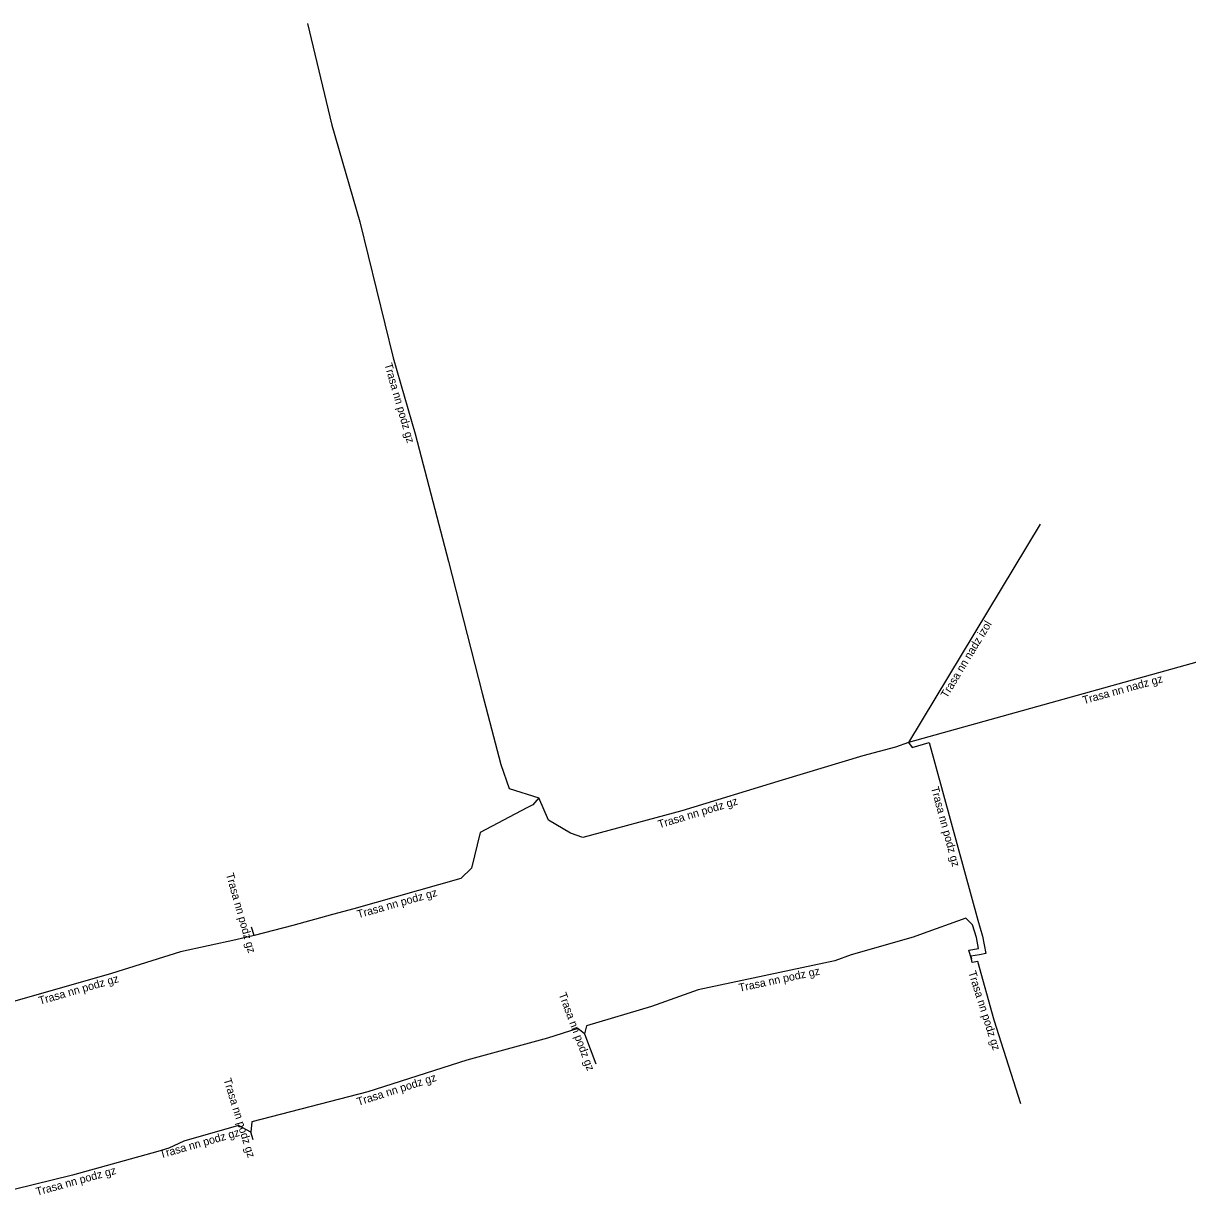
# Model space of a CAD drawing. Extents: x -690200 to -689130, y -975255 to -974631.
# Drawn here: x -689979.9 to -689907.2, y -975138.2 to -975064.6 of the extents above; entities that cross this region are included whole.
import ezdxf

# ---------------------------------------------------------------- set-up
doc = ezdxf.new("R2010")
doc.units = 0
doc.layers.add('Popiskový text - Ostatní atributy Trasy', color=7, linetype='Continuous')
doc.layers.add('Spojnice NN', color=7, linetype='Continuous')

msp = doc.modelspace()

# ---------------------------------------------------------------- linework, layer by layer
at = {"layer": 'Spojnice NN'}
for points in [[(-689962.19, -975064.64), (-689960.67, -975070.98), (-689958.92, -975077.03), (-689956.83, -975085.53), (-689955.46, -975090.27), (-689953.38, -975098.24), (-689951.28, -975106.48), (-689950.11, -975110.93), (-689949.59, -975112.43), (-689947.73, -975113.02)], [(-689916.41, -975095.912), (-689924.64, -975109.55)], [(-689895.57, -975101.45), (-689924.64, -975109.55)], [(-689924.64, -975109.55), (-689925.44, -975109.86), (-689927.49, -975110.39), (-689932.53, -975111.91), (-689938.8, -975113.82), (-689944.98, -975115.5), (-689945.76, -975115.23), (-689947.13, -975114.41), (-689947.73, -975113.02)], [(-689924.64, -975109.55), (-689924.4, -975109.87), (-689923.34, -975109.56), (-689920.305, -975120.666), (-689920.005, -975121.653), (-689919.808, -975122.74), (-689920.201, -975122.816), (-689920.733, -975122.902), (-689920.707, -975123.1)], [(-689947.73, -975113.02), (-689948.11, -975113.45), (-689948.49, -975113.64), (-689951.41, -975115.19), (-689951.94, -975117.4), (-689952.61, -975118.05), (-689959.29, -975119.95), (-689960.62, -975120.3), (-689963.11, -975121), (-689965.53, -975121.62)], [(-689920.707, -975123.1), (-689920.876, -975122.524), (-689920.273, -975122.433), (-689920.395, -975121.747), (-689920.635, -975120.954), (-689921.05, -975120.54), (-689923.94, -975121.58), (-689924.35, -975121.73), (-689928.21, -975122.82), (-689929.24, -975123.2), (-689937.78, -975125.02), (-689940.69, -975126.06), (-689944.76, -975127.25), (-689944.88, -975127.77)], [(-689965.53, -975121.62), (-689966.66, -975121.88), (-689970.12, -975122.63), (-689974.43, -975123.98), (-689981.07, -975125.89), (-689984.56, -975126.73), (-689985.1, -975126.41)], [(-689965.53, -975121.62), (-689965.68, -975121.09)], [(-689917.62, -975132.13), (-689919.28, -975126.9), (-689920.295, -975123.247), (-689920.648, -975123.311), (-689920.707, -975123.1)], [(-689944.88, -975127.77), (-689945.29, -975127.42), (-689947.19, -975128.04), (-689952.23, -975129.41), (-689958.43, -975131.39), (-689965.67, -975133.26), (-689965.74, -975133.9)], [(-689944.88, -975127.77), (-689944.18, -975129.64)], [(-689965.74, -975133.9), (-689966.5, -975133.48), (-689969.92, -975134.46)], [(-689965.59, -975134.38), (-689965.74, -975133.9)], [(-689969.92, -975134.46), (-689970.85, -975134.91), (-689971.54, -975135.12), (-689976.87, -975136.59), (-689980.52, -975137.49), (-689980.66, -975138.17)]]:
    msp.add_lwpolyline(points, dxfattribs=at)

# ---------------------------------------------------------------- texts
at = {"layer": 'Popiskový text - Ostatní atributy Trasy'}
for s, rotation, p in [('Trasa nn podz gz', 286.12086, (-689957.391, -975085.93)), ('Trasa nn nadz izol', 58.89066, (-689922.237, -975106.826)), ('Trasa nn nadz gz', 15.56985, (-689913.682, -975107.171)), ('Trasa nn podz gz', 285.28436, (-689923.243, -975112.383)), ('Trasa nn podz gz', 16.94206, (-689940.205, -975114.928)), ('Trasa nn podz gz', 285.80251, (-689967.291, -975117.786)), ('Trasa nn podz gz', 15.8774, (-689959.012, -975120.547)), ('Trasa nn podz gz', 12.0306, (-689935.19, -975125.133)), ('Trasa nn podz gz', 287.60942, (-689920.908, -975123.918)), ('Trasa nn podz gz', 16.04791, (-689978.91, -975125.945)), ('Trasa nn podz gz', 290.52246, (-689946.504, -975125.286)), ('Trasa nn podz gz', 287.35402, (-689967.447, -975130.617)), ('Trasa nn podz gz', 17.71113, (-689959.013, -975132.259)), ('Trasa nn podz gz', 15.98964, (-689971.356, -975135.548)), ('Trasa nn podz gz', 15.41872, (-689979.087, -975137.875))]:
    msp.add_text(s, height=0.5, rotation=rotation, dxfattribs=at).set_placement(p)

doc.saveas('drawing.dxf')
